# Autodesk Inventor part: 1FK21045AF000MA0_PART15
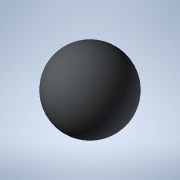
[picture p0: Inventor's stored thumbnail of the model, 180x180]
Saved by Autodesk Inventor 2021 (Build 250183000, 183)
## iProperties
Created: 2025-04
Part Number: 1FK21045AF000MA0_PART15
Material: Generic
Catalog Web Link: www.3dfindit.com
Description: -Servo synchronous motor
Document SubType Name: Modeling
Designer: psAdmin
Mass: 0.137258 g
Surface Area: 1.2868 cm^2
Volume: 0.137258 cm^3
Density: 1 g/cm^3
Appearance: PSOLRGB-212-217-219
Category: PARTsolutions
Title: 1FK21045AF000MA0_PART15
Author: Cadenas PARTsolutions
Comments: Servo synchronous motor
Sending System: PARTsolutions
Preprocessor: ST-DEVELOPER v19.3
PSOL_IDENT_0: {$CADENAS_DATA/23d-libs/siemens_ag/_cat_/8b/0a/1fk21045af000ma0.prj},216 {VTYP=3D},{NB=1FK21045AF000
PSOL_IDENT_1: MA0_PART15},{LINA=1FK21045AF000MA0_PART15},{NN=1FK21045AF000MA0_PART15},{NOPRJ=TRUE},{DATE=19.08.202
PSOL_IDENT_2: 5 14:00:48},{GEOMDATE=30.07.2025 02:00:28},{VERSION=},{LINEID=10},{WBVAR=},{WBNUMERIC=}  {NB=1FK2104
PSOL_IDENT_3: 5AF000MA0_PART15},{LINA=1FK21045AF000MA0_PART15},{KT=DUMMY},{PREVIEW=../../../_pool_/a9/69/p_d211_xx
PSOL_IDENT_4: _00818j.png},{DESCSHORT=SIMOTICS S-1FK2 HD, SINAMICS S210 3AC 400V-480V, 2.4 Nm, 3000 rpm},{DESCLONG=
PSOL_IDENT_5: SIMOTICS S-1FK2 HD servo motor M0=2.4 Nm; PN = 0.75 kW at nN=3000 rpm (380-480 V); PN = 0.375 kW at
PSOL_IDENT_6: nN=1500 rpm (200-240 V); degree of protection IP64; cylindrical shaft D19x40mm; absolute encoder 22-
PSOL_IDENT_7: bit + 12-bit multiturn (encoder AM22DQC); with OCC interface; plug size M17, rotatable; SIMOTICS S-1
PSOL_IDENT_8: FK2 servomotorfor a wide range of uses in industrial environments. SIMOTICS S‑1FK2 servomotors are c
PSOL_IDENT_9: ompact synchronous motors with a high dynamic performance that set themselves apart as a result of t
PSOL_IDENT_10: heir high power density, degree of protection and overload capability. The motors are available in t
PSOL_IDENT_11: wo variants: as High Dynamic variant (highest dynamic performance as a result of the low intrinsic m
PSOL_IDENT_12: oment of inertia for applications demanding a high dynamic performance with low moved masses) - and
PSOL_IDENT_13: as Compact variant (precise and stable closed-loop control for medium up to large moved masses as a
PSOL_IDENT_14: result of a medium intrinsic moment of inertia). SIMOTICSS‑1FK2 servomotors fully exploit their stre
PSOL_IDENT_15: ngths in a system with the SINAMICSS210 frequency converter and simple connection using the one cabl
PSOL_IDENT_16: e connection (OCC). Advantages include the short control and positioning times, fast and precise cor
PSOL_IDENT_17: rection of disturbing quantities as well as stable control with a high dynamic performance. The serv
PSOL_IDENT_18: o motors can be configured to address a wide range of requirements. For example with and without hol
PSOL_IDENT_19: ding brake, IP64 or IP65 degree of protection, singleturn or multiturn absolute encoders - to name j
PSOL_IDENT_20: ust a few. Further, the servomotors are available in different shaft heights extending from 20 to 10
PSOL_IDENT_21: 0. A shaft sealing ring is available to achieve an IP65 degree of protection and for subsequent moun
PSOL_IDENT_22: ting at the motor or as spare part. SIMOTICS - the optimum motor for each and every motion control a
PSOL_IDENT_23: pplication.},{INTNO=195125050112},{SUPPLIERALTNO=1FK2104-5AF00-0MA0},{MANUID=1FK21045AF000MA0},{MANU
PSOL_IDENT_24: NAME=Siemens},{MANUTYPEDESC=Synchronous motor 1FK2-HD 2.4 NM},{AAU732=SIMOTICS},{AAO057=S-1FK2},{AAU
PSOL_IDENT_25: 734=SIMOTICS S-1FK2 HD servo motor M0=2.4 Nm; PN = 0.75 kW at nN=3000 rpm (380-480 V); PN = 0.375 kW
PSOL_IDENT_26: at nN=1500 rpm (200-240 V); degree of protection IP64; cylindrical shaft D19x40mm; absolute encoder
PSOL_IDENT_27: 22-bit + 12-bit multiturn (encoder AM22DQC); with OCC interface; plug size M17, rotatable;},{AAW338=
PSOL_IDENT_28: Synchronous motor 1FK2-HD 2.4 NM},{AAO742=SIMOTICS},{AAO663=4042948692912},{NOCUPEROU=1},{PRICEQUANT
PSOL_IDENT_29: ITY=1},{QUANTITYMIN=1},{QUANTITYINT=1},{CTN=85015100},{COO=DE},{AAO676=1FK2104-5AF00-0MA0},{AAO677=S
PSOL_IDENT_30: iemens AG},{ORDERUNIT=C62},{CONTENTUNIT=C62}
NB: 1FK21045AF000MA0_PART15
NT: Servo synchronous motor
NBSYN: $MANUID._PART15
LINA: 1FK21045AF000MA0_PART15
CATALOG: SIEMENS
PREVIEW: ../../../_pool_/a9/69/p_d211_xx_00818j.png
DESCSHORT: SIMOTICS S-1FK2 HD, SINAMICS S210 3AC 400V-480V, 2.4 Nm, 3000 rpm
DESCLONG: SIMOTICS S-1FK2 HD servo motor M0=2.4 Nm; PN = 0.75 kW at nN=3000 rpm (380-480 V); PN = 0.375 kW at nN=1500 rpm (200-240 V); degree of protection IP64; cylindri
INTNO: 195125050112
SUPPLIERALTNO: 1FK2104-5AF00-0MA0
MANUID: 1FK21045AF000MA0
MANUNAME: Siemens
MANUTYPEDESC: Synchronous motor 1FK2-HD 2.4 NM
AAU732: SIMOTICS
AAO057: S-1FK2
AAU734: SIMOTICS S-1FK2 HD servo motor M0=2.4 Nm; PN = 0.75 kW at nN=3000 rpm (380-480 V); PN = 0.375 kW at nN=1500 rpm (200-240 V); degree of protection IP64; cylindri
AAW338: Synchronous motor 1FK2-HD 2.4 NM
AAO742: SIMOTICS
AAO663: 4042948692912.0
NOCUPEROU: 1
PRICEQUANTITY: 1
QUANTITYMIN: 1
QUANTITYINT: 1
CTN: 85015100
COO: DE
ARTICLENO: 1FK21045AF000MA0_PART15
BOMINFO: 1FK21045AF000MA0_PART15
CREATOR: CADENAS GmbH
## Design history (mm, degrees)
feature "2025_04_17_15_40_42_0766"
body "Solid1"
